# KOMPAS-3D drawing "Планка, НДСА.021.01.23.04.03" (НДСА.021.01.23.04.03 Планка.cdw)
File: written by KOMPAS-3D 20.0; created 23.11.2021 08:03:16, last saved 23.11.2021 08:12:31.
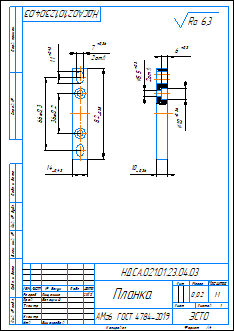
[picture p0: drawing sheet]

Sheet 1: A4, portrait

Document properties: Параметр неуказанной шероховатости: Ra 6,3; PLM_CDWXDTO: <item xmlns="http://appius.ru/pdm" xmlns:xs="http://www.w3.org/2001/XMLSchema" xmlns:xsi="http://www.w3.org/2001/XMLSchema-instance" xsi:type="item">  <element xmlns:d2p1="http://v8.1c.ru/8.1/data/enterprise/current-config" xsi:type="d2p1:CatalogRef.aps_Элемен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; PDM_DOCXDTO: <item xmlns="http://appius.ru/pdm" xmlns:xs="http://www.w3.org/2001/XMLSchema" xmlns:xsi="http://www.w3.org/2001/XMLSchema-instance" xsi:type="item">  <element xmlns:d2p1="http://v8.1c.ru/8.1/data/enterprise/current-config" xsi:type="d2p1:CatalogRef.aps_Элемен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; PDM_ITEMXDTO: <item xmlns="http://appius.ru/pdm" xmlns:xs="http://www.w3.org/2001/XMLSchema" xmlns:xsi="http://www.w3.org/2001/XMLSchema-instance" xsi:type="item">  <element xmlns:d2p1="http://v8.1c.ru/8.1/data/enterprise/current-config" xsi:type="d2p1:CatalogRef.aps_Элемен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; Масса: 0.0238069

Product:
- Part/product: Планка  | designation НДСА.021.01.23.04.03
    Материал: АМг6  ГОСТ 4784-2019 (density 2640 kg/m3)
    Масса: 0.0238069
    additional columns: <item xmlns="http://appius.ru/pdm" xmlns:xs="http://www.w3.org/2001/XMLSchema" x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; <item xmlns="http://appius.ru/pdm" xmlns:xs="http://www.w3.org/2001/XMLSchema" x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
    source file: НДСА.021.01.23.04.03 Планка.cdw

Title block, sheet 1: Наименование: Планка; designation: НДСА.021.01.23.04.03; Материал: АМг6  ГОСТ 4784-2019; Масса: 0,02; Количество листов документа: 1; organisation: ЭСТО; Форматы листов документа: A4; stored path: C:\Users\s.pischagina\Desktop\PLM\НДСА.021.01.23.04.03 Планка.cdw; Разработал: Пищагина; Проверил: Белецкий; Утвердил: Виноградов; Разработал, date: 23.11.21

Views: Вид 1, Снизу, Проекционный вид 2, Местный разрез 1
Referenced files in C:\Users\s.pischagina\Desktop\PLM\: НДСА.021.01.23.04.03 Планка.m3d
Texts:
  Ra 6,3
  НДСА.021.01.23.04.03 Планка
Dimensions and other numbers on the sheet: 36±0,2; 66±0,3; 82; 11; 7; 2отв; 14; 10; 6; 5,5; 1:1; 1; 0,02; 23.11.21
